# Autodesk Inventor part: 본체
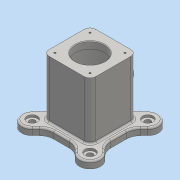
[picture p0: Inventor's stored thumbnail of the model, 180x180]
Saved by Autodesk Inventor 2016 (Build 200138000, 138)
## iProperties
Created: 2019-11
Part Number: 본체
Material: 일반
Document SubType Name: Modeling
Designer: user
Density: 1 g/cm^3
Appearance: 기본값
Author: user
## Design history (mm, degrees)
sketch "스케치2"
  geometry: L1 (-49, 49)-(49, 49); L2 (49, 49)-(49, -49); L3 (49, -49)-(-49, -49); L4 (-49, -49)-(-49, 49); L5 (-49, 49)-(49, -49); L6 (49, 49)-(-49, -49); L7 (-49.497, -49.497)-(49.497, 49.497); L8 (-36.77, -62.225)-(62.225, 36.77); L9 (36.77, 62.225)-(-62.225, -36.77); L10 (49.497, -49.497)-(-49.497, 49.497); L11 (62.225, -36.77)-(-36.77, 62.225); L12 (-62.225, 36.77)-(36.77, -62.225); A1 r 70 centre (0, 0) between (49.497, 49.497) and (-49.497, 49.497); A2 r 18 centre (-49.497, -49.497) between (-62.225, -36.77) and (-36.77, -62.225); A3 r 18 centre (49.497, 49.497) between (62.225, 36.77) and (36.77, 62.225); A4 r 18 centre (49.497, -49.497) between (36.77, -62.225) and (62.225, -36.77); A5 r 18 centre (-49.497, 49.497) between (-36.77, 62.225) and (-62.225, 36.77); 2 further points
  constraints: 28 end point, 10 point on circle, 8 tangent, 6 midpoint, 5 centre point, 4 parallel, 2 point on line, 1 coincident, 1 horizontal, 1 perpendicular
  dimensions: "d0" = 98 distance of L2.end L3.end; "d1" = 98 distance of L1.end L2.end; "d2" = 140 diameter of A1; "d3" = 36 diameter of A3; "d4" = 36 diameter of A5
extrude "돌출1" new body sketch "스케치2" distance "d5" = 12; taper "d6" = 0 deg
sketch "스케치4"
  geometry: A1 r 18 centre (-49.497, 49.497) between (-36.77, 62.225) and (-62.225, 36.77) reference; A2 r 18 centre (49.497, 49.497) between (62.225, 36.77) and (36.77, 62.225) reference; A3 r 18 centre (49.497, -49.497) between (36.77, -62.225) and (62.225, -36.77) reference; A4 r 18 centre (-49.497, -49.497) between (-62.225, -36.77) and (-36.77, -62.225) reference; 5 further points
  constraints: 4 coincident
hole "구멍2" sketch "스케치4" at (-49.497, 49.497), (49.497, 49.497), (49.497, -49.497), (-49.497, -49.497) diameter "d14" = 10; stored, may be unused: countersink angle "d18" = 90 deg, drill point angle "d20" = 118 deg; dims "d15" = 6, "d16" = 18, "d17" = 4, "d19" = 8
sketch "스케치5"
  geometry: L1 (-40, 40)-(40, 40); L2 (40, 40)-(40, -40); L3 (40, -40)-(-40, -40); L4 (-40, -40)-(-40, 40); L5 (-40, 40)-(40, -40); L6 (40, 40)-(-40, -40); 1 further point
  constraints: 12 end point, 2 midpoint, 2 parallel, 1 horizontal, 1 perpendicular
  dimensions: "d21" = 80 distance of L2.end L3.end; "d22" = 80 distance of L1.end L2.end
extrude "돌출2" join sketch "스케치5" distance "d23" = 98; taper "d24" = 0 deg
node "작업 평면1"
sketch "스케치6"
  geometry: C1 r 20 at (0, 61); 1 further point
  constraints: 1 centre point, 1 vertical alignment
  dimensions: "d26" = 61 distance of point (0, 0) C1.centre; "d27" = 40 diameter of C1
extrude "돌출3" join sketch "스케치6" stored distance "d28" = 98; taper "d29" = 0 deg
node "작업 평면2"
sketch "스케치8"
  geometry: 2 further points
  constraints: 1 vertical alignment
  dimensions: "d31" = 61 distance of point (0, 61) point (0, 0)
hole "구멍3" sketch "스케치8" at (0, 61) diameter "d32" = 25; stored, may be unused: countersink angle "d36" = 90 deg, drill point angle "d38" = 118 deg; dims "d33" = 6, "d34" = 30, "d35" = 8, "d37" = 55
sketch "스케치9"
  geometry: C1 r 25 at (0, 0); 1 further point
  constraints: 1 centre point, 1 coincident
  dimensions: "d39" = 50 diameter of C1
extrude "돌출4" cut sketch "스케치9" distance "d40" = 12; taper "d41" = 0 deg
sketch "스케치10"
  geometry: C1 r 35 at (0, 0); 1 further point
  constraints: 1 centre point, 1 coincident
  dimensions: "d42" = 70 diameter of C1
extrude "돌출5" cut sketch "스케치10" distance "d43" = 86; taper "d44" = 0 deg
sketch "스케치11"
  geometry: C1 r 25 at (0, 0); 1 further point
  constraints: 1 centre point, 1 coincident
  dimensions: "d45" = 50 diameter of C1
extrude "돌출6" cut sketch "스케치11" distance "d46" = 12; taper "d47" = 0 deg
sketch "스케치12"
  geometry: L1 (30, -30)-(-30, -30); L2 (-30, -30)-(-30, 30); L3 (-30, 30)-(30, 30); L4 (30, 30)-(30, -30); L5 (30, -30)-(-30, 30); L6 (-30, -30)-(30, 30); 2 further points
  constraints: 12 end point, 2 midpoint, 2 parallel, 1 coincident, 1 horizontal, 1 perpendicular
  dimensions: "d48" = 60 distance of L2.end L3.end; "d49" = 60 distance of L1.end L2.end
hole "구멍4" sketch "스케치12" at (30, -30) diameter "d50" = 3.242; stored, may be unused: countersink angle "d54" = 90 deg, drill point angle "d56" = 118 deg; dims "d51" = 8, "d52" = 30, "d53" = 8, "d55" = 10
node "작업 평면3"
fillet "모깎기1" dims "d61" = 10
fillet "모깎기2" dims "d62" = 25
fillet "모깎기3" dims "d63" = 3
chamfer "모따기1" distance "d64" = 1; stored, may be unused: second distance "d65" = 2, angle "d66" = 45 deg
fillet "모깎기4" dims "d67" = 3
sketch "스케치13"
  geometry: L1 (60, -98)-(0, -98) reference; L2 (16.811, 12)-(43.189, 12) reference; 3 further points
  constraints: 1 midpoint, 1 vertical alignment, 1 other
  dimensions: "d68" = 10 distance from line of L1 point (30, -88)
feature "엠보싱1" sketch "스케치13" dims "d0" = 98, "d1" = 98, "d2" = 140, "d3" = 36, "d4" = 36, "d69" = 0.5, "d70" = 0
fillet "모깎기5" dims "d71" = 3
fillet "모깎기6" dims "d72" = 3
node "솔리드1"
pattern_circular "원형 패턴1" dims angle "d58" = 360 deg
mirror "대칭1"
other parameters: "d25" = 55, "d30" = 55, "d60" = 55
